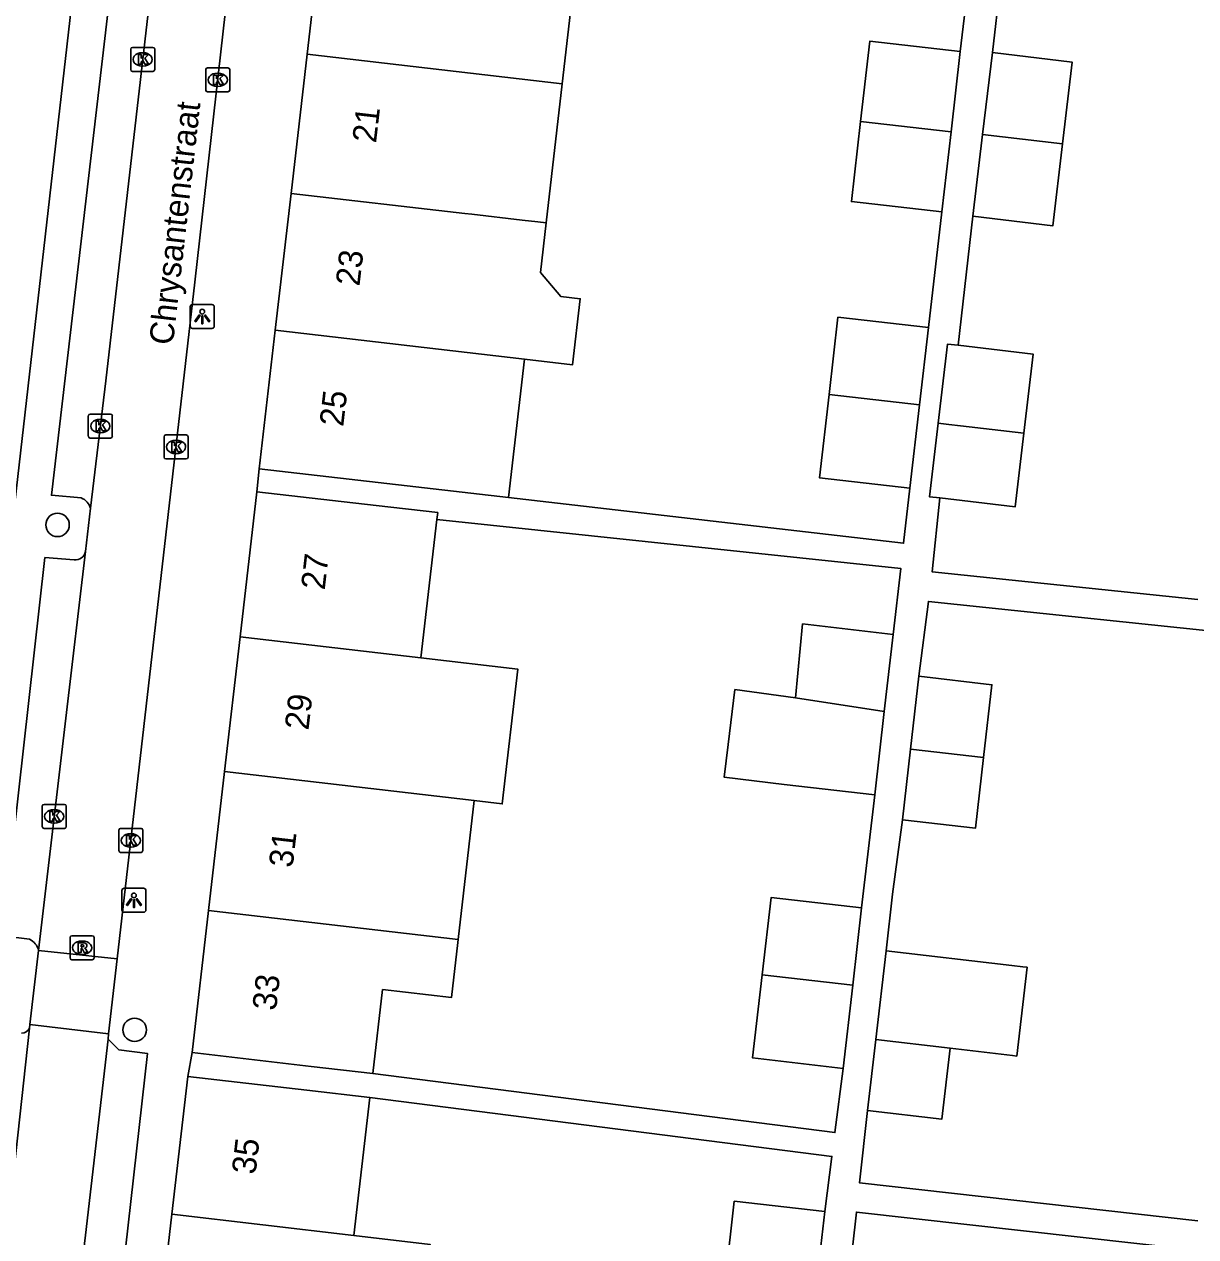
# Model space of a CAD drawing. Extents: x 161696 to 162377, y 380761 to 381673.
# Drawn here: x 162078 to 162126.9, y 381016.9 to 381067.5 of the extents above; entities that cross this region are included whole.
import ezdxf

# ---------------------------------------------------------------- set-up
doc = ezdxf.new("R2010")
doc.units = 0
for name, color, linetype in [('IMGEO_Boom', 7, 'Continuous'), ('IMGEO_Kolk', 7, 'Continuous'), ('IMGEO_Lichtpunt', 7, 'Continuous'), ('IMGEO_Openbare_ruimte_label', 7, 'Continuous'), ('IMGEO_Pand', 7, 'Continuous'), ('IMGEO_Pand_nummerreeks', 7, 'Continuous'), ('IMGEO_Rijbaan_lokaal_open', 7, 'Continuous'), ('IMGEO_Rioolput', 7, 'Continuous'), ('IMGEO_Voetpad_open', 7, 'Continuous')]:
    doc.layers.add(name, color=color, linetype=linetype)

msp = doc.modelspace()

# ---------------------------------------------------------------- linework, layer by layer
at = {"layer": 'IMGEO_Boom'}
for centre in [(162079.43, 381046.631), (162082.645, 381025.565)]:
    msp.add_circle(centre, 0.489, dxfattribs=at)
at = {"layer": 'IMGEO_Kolk'}
for p, q in [((162082.48, 381065.625), (162082.48, 381066.477)), ((162082.555, 381066.551), (162083.407, 381066.551)), ((162082.968, 381066.331), (162082.993, 381066.331)), ((162083.481, 381066.477), (162083.481, 381065.625)), ((162082.991, 381065.771), (162082.966, 381065.771)), ((162083.407, 381065.551), (162082.555, 381065.551)), ((162085.61, 381064.773), (162085.61, 381065.625)), ((162085.685, 381065.699), (162086.537, 381065.699)), ((162086.098, 381065.479), (162086.123, 381065.479)), ((162086.611, 381065.625), (162086.611, 381064.773)), ((162086.121, 381064.919), (162086.096, 381064.919)), ((162086.537, 381064.699), (162085.685, 381064.699)), ((162080.714, 381050.327), (162080.714, 381051.179)), ((162080.789, 381051.253), (162081.641, 381051.253)), ((162081.715, 381051.179), (162081.715, 381050.327)), ((162081.202, 381051.033), (162081.227, 381051.033)), ((162081.641, 381050.253), (162080.789, 381050.253)), ((162081.225, 381050.473), (162081.2, 381050.473)), ((162083.871, 381049.457), (162083.871, 381050.309)), ((162083.946, 381050.383), (162084.798, 381050.383)), ((162084.359, 381050.163), (162084.384, 381050.163)), ((162084.872, 381050.309), (162084.872, 381049.457)), ((162084.382, 381049.603), (162084.357, 381049.603)), ((162084.798, 381049.383), (162083.946, 381049.383)), ((162078.792, 381034.042), (162078.792, 381034.894)), ((162078.867, 381034.968), (162079.719, 381034.968)), ((162079.793, 381034.894), (162079.793, 381034.042)), ((162079.28, 381034.748), (162079.305, 381034.748)), ((162079.719, 381033.968), (162078.867, 381033.968)), ((162079.303, 381034.188), (162079.278, 381034.188)), ((162081.987, 381033.04), (162081.987, 381033.892)), ((162082.062, 381033.966), (162082.914, 381033.966)), ((162082.988, 381033.892), (162082.988, 381033.04)), ((162082.475, 381033.746), (162082.5, 381033.746)), ((162082.914, 381032.966), (162082.062, 381032.966)), ((162082.498, 381033.186), (162082.473, 381033.186))]:
    msp.add_line(p, q, dxfattribs=at)
for points in [[(162082.48, 381065.625), (162082.48, 381066.477)], [(162082.555, 381066.551), (162083.407, 381066.551)], [(162082.801, 381066.251), (162082.924, 381066.251), (162082.924, 381066.1), (162083.054, 381066.251), (162083.218, 381066.251), (162083.072, 381066.1), (162083.225, 381065.851), (162083.073, 381065.851), (162082.988, 381066.015), (162082.924, 381065.948), (162082.924, 381065.851), (162082.801, 381065.851), (162082.801, 381066.251)], [(162083.481, 381066.477), (162083.481, 381065.625)], [(162083.407, 381065.551), (162082.555, 381065.551)], [(162085.61, 381064.773), (162085.61, 381065.625)], [(162085.685, 381065.699), (162086.537, 381065.699)], [(162085.931, 381065.399), (162086.054, 381065.399), (162086.054, 381065.248), (162086.184, 381065.399), (162086.348, 381065.399), (162086.202, 381065.248), (162086.355, 381064.999), (162086.203, 381064.999), (162086.118, 381065.163), (162086.054, 381065.096), (162086.054, 381064.999), (162085.931, 381064.999), (162085.931, 381065.399)], [(162086.611, 381065.625), (162086.611, 381064.773)], [(162086.537, 381064.699), (162085.685, 381064.699)], [(162080.714, 381050.327), (162080.714, 381051.179)], [(162080.789, 381051.253), (162081.641, 381051.253)], [(162081.715, 381051.179), (162081.715, 381050.327)], [(162081.035, 381050.953), (162081.158, 381050.953), (162081.158, 381050.802), (162081.288, 381050.953), (162081.452, 381050.953), (162081.306, 381050.802), (162081.459, 381050.553), (162081.307, 381050.553), (162081.222, 381050.717), (162081.158, 381050.65), (162081.158, 381050.553), (162081.035, 381050.553), (162081.035, 381050.953)], [(162081.641, 381050.253), (162080.789, 381050.253)], [(162083.871, 381049.457), (162083.871, 381050.309)], [(162083.946, 381050.383), (162084.798, 381050.383)], [(162084.192, 381050.083), (162084.315, 381050.083), (162084.315, 381049.932), (162084.445, 381050.083), (162084.609, 381050.083), (162084.463, 381049.932), (162084.616, 381049.683), (162084.464, 381049.683), (162084.379, 381049.847), (162084.315, 381049.78), (162084.315, 381049.683), (162084.192, 381049.683), (162084.192, 381050.083)], [(162084.872, 381050.309), (162084.872, 381049.457)], [(162084.798, 381049.383), (162083.946, 381049.383)], [(162078.792, 381034.042), (162078.792, 381034.894)], [(162078.867, 381034.968), (162079.719, 381034.968)], [(162079.793, 381034.894), (162079.793, 381034.042)], [(162079.113, 381034.668), (162079.236, 381034.668), (162079.236, 381034.517), (162079.366, 381034.668), (162079.53, 381034.668), (162079.384, 381034.517), (162079.537, 381034.268), (162079.385, 381034.268), (162079.3, 381034.432), (162079.236, 381034.365), (162079.236, 381034.268), (162079.113, 381034.268), (162079.113, 381034.668)], [(162079.719, 381033.968), (162078.867, 381033.968)], [(162081.987, 381033.04), (162081.987, 381033.892)], [(162082.062, 381033.966), (162082.914, 381033.966)], [(162082.988, 381033.892), (162082.988, 381033.04)], [(162082.308, 381033.666), (162082.431, 381033.666), (162082.431, 381033.515), (162082.561, 381033.666), (162082.725, 381033.666), (162082.579, 381033.515), (162082.732, 381033.266), (162082.58, 381033.266), (162082.495, 381033.43), (162082.431, 381033.363), (162082.431, 381033.266), (162082.308, 381033.266), (162082.308, 381033.666)], [(162082.914, 381032.966), (162082.062, 381032.966)]]:
    msp.add_lwpolyline(points, dxfattribs=at)
for centre, start, end in [((162082.557, 381066.475), 91.552, 178.448), ((162082.557, 381066.475), 91.552, 178.448), ((162083.405, 381066.475), 1.552, 88.448), ((162083.405, 381066.475), 1.552, 88.448), ((162082.557, 381065.627), 181.552, 268.448), ((162082.557, 381065.627), 181.552, 268.448), ((162083.405, 381065.627), 271.552, 358.448), ((162083.405, 381065.627), 271.552, 358.448), ((162085.687, 381065.623), 91.552, 178.448), ((162085.687, 381065.623), 91.552, 178.448), ((162086.535, 381065.623), 1.552, 88.448), ((162086.535, 381065.623), 1.552, 88.448), ((162085.687, 381064.775), 181.552, 268.448), ((162085.687, 381064.775), 181.552, 268.448), ((162086.535, 381064.775), 271.552, 358.448), ((162086.535, 381064.775), 271.552, 358.448), ((162080.791, 381051.177), 91.552, 178.448), ((162080.791, 381051.177), 91.552, 178.448), ((162081.639, 381051.177), 1.552, 88.448), ((162081.639, 381051.177), 1.552, 88.448), ((162080.791, 381050.329), 181.552, 268.448), ((162080.791, 381050.329), 181.552, 268.448), ((162081.639, 381050.329), 271.552, 358.448), ((162081.639, 381050.329), 271.552, 358.448), ((162083.948, 381050.307), 91.552, 178.448), ((162083.948, 381050.307), 91.552, 178.448), ((162084.796, 381050.307), 1.552, 88.448), ((162084.796, 381050.307), 1.552, 88.448), ((162083.948, 381049.459), 181.552, 268.448), ((162083.948, 381049.459), 181.552, 268.448), ((162084.796, 381049.459), 271.552, 358.448), ((162084.796, 381049.459), 271.552, 358.448), ((162078.869, 381034.892), 91.552, 178.448), ((162078.869, 381034.892), 91.552, 178.448), ((162079.717, 381034.892), 1.552, 88.448), ((162079.717, 381034.892), 1.552, 88.448), ((162078.869, 381034.044), 181.552, 268.448), ((162078.869, 381034.044), 181.552, 268.448), ((162079.717, 381034.044), 271.552, 358.448), ((162079.717, 381034.044), 271.552, 358.448), ((162082.064, 381033.89), 91.552, 178.448), ((162082.064, 381033.89), 91.552, 178.448), ((162082.912, 381033.89), 1.552, 88.448), ((162082.912, 381033.89), 1.552, 88.448), ((162082.064, 381033.042), 181.552, 268.448), ((162082.064, 381033.042), 181.552, 268.448), ((162082.912, 381033.042), 271.552, 358.448), ((162082.912, 381033.042), 271.552, 358.448)]:
    msp.add_arc(centre, 0.0765, start, end, dxfattribs=at)
for centre, major_axis, ratio, start_param, end_param in [((162082.967, 381066.051), (-0.387, 0.002), 0.722429, 4.712389, 7.853982), ((162082.992, 381066.051), (-0.39, 0.002), 0.717154, 1.570796, 4.712389), ((162086.097, 381065.199), (-0.387, 0.002), 0.722429, 4.712389, 7.853982), ((162086.122, 381065.199), (-0.39, 0.002), 0.717154, 1.570796, 4.712389), ((162081.201, 381050.753), (-0.387, 0.002), 0.722429, 4.712389, 7.853982), ((162081.226, 381050.753), (-0.39, 0.002), 0.717154, 1.570796, 4.712389), ((162084.358, 381049.883), (-0.387, 0.002), 0.722429, 4.712389, 7.853982), ((162084.383, 381049.883), (-0.39, 0.002), 0.717154, 1.570796, 4.712389), ((162079.279, 381034.468), (-0.387, 0.002), 0.722429, 4.712389, 7.853982), ((162079.304, 381034.468), (-0.39, 0.002), 0.717154, 1.570796, 4.712389), ((162082.474, 381033.466), (-0.387, 0.002), 0.722429, 4.712389, 7.853982), ((162082.499, 381033.466), (-0.39, 0.002), 0.717154, 1.570796, 4.712389)]:
    msp.add_ellipse(centre, major_axis=major_axis, ratio=ratio, start_param=start_param, end_param=end_param, dxfattribs=at)
at = {"layer": 'IMGEO_Lichtpunt'}
for p, q in [((162084.967, 381055.73), (162084.967, 381054.923)), ((162084.967, 381055.73), (162084.967, 381054.923)), ((162085.869, 381055.825), (162085.061, 381055.825)), ((162085.869, 381055.825), (162085.061, 381055.825)), ((162085.963, 381054.923), (162085.963, 381055.73)), ((162085.963, 381054.923), (162085.963, 381055.73)), ((162085.061, 381054.829), (162085.869, 381054.829)), ((162085.061, 381054.829), (162085.869, 381054.829)), ((162082.117, 381031.375), (162082.117, 381030.568)), ((162082.117, 381031.375), (162082.117, 381030.568)), ((162083.019, 381031.47), (162082.211, 381031.47)), ((162083.019, 381031.47), (162082.211, 381031.47)), ((162083.113, 381030.568), (162083.113, 381031.375)), ((162083.113, 381030.568), (162083.113, 381031.375)), ((162082.211, 381030.474), (162083.019, 381030.474)), ((162082.211, 381030.474), (162083.019, 381030.474))]:
    msp.add_line(p, q, dxfattribs=at)
for points in [[(162085.341, 381055.394), (162085.38, 381055.366), (162085.192, 381055.104), (162085.154, 381055.131), (162085.341, 381055.394)], [(162085.443, 381055.346), (162085.49, 381055.346), (162085.49, 381055.024), (162085.443, 381055.024), (162085.443, 381055.346)], [(162085.553, 381055.366), (162085.591, 381055.393), (162085.778, 381055.131), (162085.739, 381055.103), (162085.553, 381055.366)], [(162082.491, 381031.039), (162082.53, 381031.011), (162082.342, 381030.749), (162082.304, 381030.776), (162082.491, 381031.039)], [(162082.593, 381030.991), (162082.64, 381030.991), (162082.64, 381030.669), (162082.593, 381030.669), (162082.593, 381030.991)], [(162082.703, 381031.011), (162082.741, 381031.038), (162082.928, 381030.776), (162082.889, 381030.748), (162082.703, 381031.011)]]:
    msp.add_lwpolyline(points, dxfattribs=at)
for centre in [(162085.466, 381055.528), (162082.616, 381031.173)]:
    msp.add_circle(centre, 0.0994, dxfattribs=at)
for centre, start, end in [((162085.061, 381055.73), 90, 180), ((162085.061, 381055.73), 90, 180), ((162085.869, 381055.73), 0, 90), ((162085.869, 381055.73), 0, 90), ((162085.061, 381054.923), 180, 270), ((162085.061, 381054.923), 180, 270), ((162085.869, 381054.923), 270, 0), ((162085.869, 381054.923), 270, 360), ((162082.211, 381031.375), 90, 180), ((162082.211, 381031.375), 90, 180), ((162083.019, 381031.375), 0, 90), ((162083.019, 381031.375), 0, 90), ((162082.211, 381030.568), 180, 270), ((162082.211, 381030.568), 180, 270), ((162083.019, 381030.568), 270, 0), ((162083.019, 381030.568), 270, 360)]:
    msp.add_arc(centre, 0.0946, start, end, dxfattribs=at)
at = {"layer": 'IMGEO_Pand'}
for points in [[(162089.842, 381066.266), (162090.553, 381072.412)], [(162101.193, 381071.182), (162100.482, 381065.034)], [(162112.924, 381063.463), (162113.308, 381066.809), (162117.083, 381066.376)], [(162089.171, 381060.461), (162089.842, 381066.266)], [(162100.482, 381065.034), (162089.842, 381066.266)], [(162117.083, 381066.376), (162116.7, 381063.031)], [(162118.015, 381062.918), (162118.421, 381066.332)], [(162118.421, 381066.332), (162121.756, 381065.935), (162121.35, 381062.522)], [(162099.811, 381059.23), (162100.482, 381065.034)], [(162116.316, 381059.685), (162112.541, 381060.118), (162112.924, 381063.463)], [(162116.7, 381063.031), (162112.924, 381063.463)], [(162116.7, 381063.031), (162116.316, 381059.685)], [(162117.609, 381059.505), (162118.015, 381062.918)], [(162121.35, 381062.522), (162118.015, 381062.918)], [(162121.35, 381062.522), (162120.944, 381059.108), (162117.609, 381059.505)], [(162088.511, 381054.749), (162089.171, 381060.461)], [(162099.811, 381059.23), (162099.462, 381059.27), (162098.804, 381059.347), (162096.715, 381059.588), (162096.412, 381059.623), (162089.171, 381060.461)], [(162098.907, 381053.545), (162100.912, 381053.313), (162101.231, 381056.068), (162100.42, 381056.162), (162099.883, 381056.792), (162099.571, 381057.157), (162099.811, 381059.23)], [(162111.608, 381052.074), (162111.977, 381055.292), (162115.752, 381054.859)], [(162087.843, 381048.974), (162088.511, 381054.749)], [(162088.511, 381054.749), (162098.907, 381053.545)], [(162115.752, 381054.859), (162115.383, 381051.637)], [(162116.993, 381054.124), (162116.551, 381054.177), (162116.158, 381050.877)], [(162119.732, 381050.461), (162120.124, 381053.751), (162116.993, 381054.124)], [(162098.244, 381047.771), (162098.907, 381053.545)], [(162114.985, 381048.168), (162111.21, 381048.601), (162111.608, 381052.074)], [(162115.383, 381051.637), (162111.608, 381052.074)], [(162115.383, 381051.637), (162114.985, 381048.168)], [(162116.231, 381047.756), (162115.793, 381047.808), (162116.158, 381050.877)], [(162116.158, 381050.877), (162116.599, 381050.826), (162117.09, 381050.769), (162119.732, 381050.461)], [(162116.231, 381047.756), (162119.366, 381047.382), (162119.732, 381050.461)], [(162098.244, 381047.771), (162092.81, 381048.4), (162087.843, 381048.974)], [(162087.046, 381041.954), (162087.747, 381048.013)], [(162087.747, 381048.013), (162092.714, 381047.439), (162095.285, 381047.142), (162095.251, 381046.849)], [(162095.251, 381046.849), (162094.585, 381041.081)], [(162110.205, 381039.42), (162110.508, 381042.498), (162114.283, 381042.065)], [(162086.398, 381036.348), (162087.046, 381041.954)], [(162087.046, 381041.954), (162094.585, 381041.081)], [(162114.283, 381042.065), (162113.914, 381038.844)], [(162094.585, 381041.081), (162098.627, 381040.613), (162097.976, 381034.991), (162096.808, 381035.126)], [(162115.006, 381037.278), (162115.354, 381040.313)], [(162118.052, 381036.923), (162118.401, 381039.963), (162115.354, 381040.313)], [(162113.516, 381035.374), (162109.741, 381035.807), (162107.232, 381036.108), (162107.401, 381037.466), (162107.686, 381039.759), (162110.205, 381039.42)], [(162113.914, 381038.844), (162110.205, 381039.42)], [(162113.914, 381038.844), (162113.516, 381035.374)], [(162114.668, 381034.328), (162115.006, 381037.278)], [(162114.668, 381034.328), (162117.714, 381033.978), (162118.052, 381036.923)], [(162118.052, 381036.923), (162115.006, 381037.278)], [(162085.727, 381030.539), (162086.398, 381036.348)], [(162096.808, 381035.126), (162086.398, 381036.348)], [(162096.139, 381029.333), (162096.808, 381035.126)], [(162108.82, 381027.865), (162109.189, 381031.082), (162112.964, 381030.649)], [(162085.042, 381024.616), (162085.727, 381030.539)], [(162096.139, 381029.333), (162085.727, 381030.539)], [(162112.964, 381030.649), (162112.595, 381027.428)], [(162092.583, 381023.744), (162092.988, 381027.242), (162095.859, 381026.91), (162096.125, 381029.213), (162096.139, 381029.333)], [(162113.555, 381025.158), (162113.987, 381028.861)], [(162116.655, 381024.796), (162119.264, 381024.491), (162119.44, 381024.47), (162119.873, 381028.174), (162119.697, 381028.194), (162119.233, 381028.249), (162113.987, 381028.861)], [(162112.197, 381023.958), (162108.422, 381024.391), (162108.82, 381027.865)], [(162112.595, 381027.428), (162108.82, 381027.865)], [(162112.595, 381027.428), (162112.197, 381023.958)], [(162113.21, 381022.199), (162113.555, 381025.158)], [(162113.21, 381022.199), (162116.31, 381021.837), (162116.655, 381024.796)], [(162116.655, 381024.796), (162113.555, 381025.158)], [(162092.583, 381023.744), (162090.009, 381024.042), (162085.042, 381024.616)], [(162084.196, 381017.874), (162084.861, 381023.624)], [(162084.861, 381023.624), (162089.828, 381023.05), (162092.453, 381022.746)], [(162091.782, 381016.988), (162092.453, 381022.746)], [(162107.286, 381015.177), (162107.658, 381018.417), (162111.433, 381017.984)], [(162083.524, 381012.063), (162084.196, 381017.874)], [(162084.196, 381017.874), (162091.782, 381016.988)], [(162111.433, 381017.984), (162111.061, 381014.736)], [(162094.295, 381010.804), (162094.971, 381016.616), (162091.782, 381016.988)]]:
    msp.add_lwpolyline(points, dxfattribs=at)
at = {"layer": 'IMGEO_Rijbaan_lokaal_open'}
for points in [[(162086.824, 381071.549), (162085.16, 381056.755), (162081.92, 381028.524)], [(162080.81, 381047.325), (162081.438, 381052.634), (162083.429, 381069.944)], [(162080.597, 381045.518), (162080.81, 381047.325)], [(162078.639, 381028.879), (162079.774, 381038.563), (162080.597, 381045.518)], [(162078.276, 381025.782), (162078.639, 381028.879)], [(162081.92, 381028.524), (162078.639, 381028.879)], [(162081.92, 381028.524), (162081.562, 381025.405)], [(162078.26, 381025.633), (162078.276, 381025.782)], [(162081.562, 381025.405), (162078.276, 381025.782)], [(162076.389, 381008.55), (162078.26, 381025.633)], [(162081.562, 381025.405), (162081.535, 381025.173)], [(162081.535, 381025.173), (162080.596, 381016.993), (162078.552, 381000), (162078.155, 380996.635)]]:
    msp.add_lwpolyline(points, dxfattribs=at)
at = {"layer": 'IMGEO_Rioolput'}
for p, q in [((162079.953, 381028.565), (162079.953, 381029.417)), ((162080.028, 381029.491), (162080.88, 381029.491)), ((162080.954, 381029.417), (162080.954, 381028.565)), ((162080.441, 381029.271), (162080.466, 381029.271)), ((162080.88, 381028.491), (162080.028, 381028.491)), ((162080.464, 381028.711), (162080.439, 381028.711))]:
    msp.add_line(p, q, dxfattribs=at)
for points in [[(162079.953, 381028.565), (162079.953, 381029.417)], [(162080.028, 381029.491), (162080.88, 381029.491)], [(162080.954, 381029.417), (162080.954, 381028.565)], [(162080.542, 381029.189), (162080.29, 381029.191), (162080.29, 381028.791)], [(162080.29, 381028.791), (162080.414, 381028.791), (162080.414, 381028.953), (162080.425, 381028.953)], [(162080.468, 381029.11), (162080.414, 381029.11), (162080.414, 381029.029)], [(162080.414, 381029.029), (162080.466, 381029.029)], [(162080.472, 381028.924), (162080.543, 381028.791), (162080.683, 381028.791), (162080.618, 381028.917)], [(162080.88, 381028.491), (162080.028, 381028.491)]]:
    msp.add_lwpolyline(points, dxfattribs=at)
for centre, radius, start, end in [((162080.03, 381029.415), 0.0765, 91.552, 178.448), ((162080.03, 381029.415), 0.0765, 91.552, 178.448), ((162080.878, 381029.415), 0.0765, 1.552, 88.448), ((162080.878, 381029.415), 0.0765, 1.552, 88.448), ((162080.424, 381028.9), 0.0533, 26.0293, 88.6989), ((162080.45, 381029.218), 0.19, 274.7715, 282.9687), ((162080.474, 381029.014), 0.0964, 77.0061, 93.1865), ((162080.488, 381029.071), 0.0378, 276.6634, 79.6772), ((162080.541, 381029.079), 0.109, 350.3612, 89.416), ((162080.539, 381029.079), 0.112, 277.5842, 350.9817), ((162080.523, 381028.864), 0.108, 29.5134, 73.7905), ((162080.03, 381028.567), 0.0765, 181.552, 268.448), ((162080.03, 381028.567), 0.0765, 181.552, 268.448), ((162080.878, 381028.567), 0.0765, 271.552, 358.448), ((162080.878, 381028.567), 0.0765, 271.552, 358.448)]:
    msp.add_arc(centre, radius, start, end, dxfattribs=at)
for centre, major_axis, ratio, start_param, end_param in [((162080.44, 381028.991), (-0.387, 0.002), 0.722429, 4.712389, 7.853982), ((162080.465, 381028.991), (-0.39, 0.002), 0.717154, 1.570796, 4.712389)]:
    msp.add_ellipse(centre, major_axis=major_axis, ratio=ratio, start_param=start_param, end_param=end_param, dxfattribs=at)
at = {"layer": 'IMGEO_Voetpad_open'}
for points in [[(162069.905, 380982.626), (162072.098, 381000), (162073.358, 381009.985), (162080.609, 381073.546)], [(162101.193, 381071.182), (162117.423, 381069.291), (162117.083, 381066.376)], [(162080.417, 381047.758), (162079.172, 381047.869), (162081.727, 381069.672), (162082.78, 381069.599)], [(162118.421, 381066.332), (162118.748, 381069.136), (162132.798, 381067.511)], [(162116.316, 381059.685), (162115.752, 381054.859)], [(162116.993, 381054.124), (162117.609, 381059.505)], [(162087.843, 381048.974), (162087.747, 381048.013)], [(162114.985, 381048.168), (162114.721, 381045.864), (162098.244, 381047.771)], [(162126.992, 381043.513), (162115.908, 381044.678), (162116.231, 381047.756)], [(162095.251, 381046.849), (162114.6, 381044.815), (162114.283, 381042.065)], [(162078.257, 381029.346), (162077.14, 381029.482), (162078.902, 381045.265), (162080.121, 381045.168)], [(162115.354, 381040.313), (162115.757, 381043.44), (162129.836, 381041.96)], [(162113.516, 381035.374), (162112.964, 381030.649)], [(162113.987, 381028.861), (162114.262, 381031.218), (162114.668, 381034.328)], [(162081.535, 381025.173), (162081.992, 381024.724), (162083.186, 381024.576), (162080.413, 381000), (162080.067, 380997.004), (162078.879, 380997.149)], [(162085.042, 381024.616), (162084.861, 381023.624)], [(162112.197, 381023.958), (162111.854, 381021.281), (162092.583, 381023.744)], [(162092.453, 381022.746), (162111.727, 381020.283), (162111.433, 381017.984)], [(162126.995, 381017.6), (162112.885, 381019.181), (162113.21, 381022.199)], [(162112.415, 381014.985), (162112.748, 381017.959), (162126.817, 381016.382)]]:
    msp.add_lwpolyline(points, dxfattribs=at)
for centre, radius, start, end in [((162080.134, 381047.107), 0.71, 17.9094, 66.5457), ((162080.167, 381045.604), 0.439, 263.9878, 348.6659), ((162077.961, 381028.714), 0.698, 13.6725, 64.893), ((162077.929, 381025.787), 0.365, 269.8135, 335.0618)]:
    msp.add_arc(centre, radius, start, end, dxfattribs=at)

# ---------------------------------------------------------------- texts
at = {"layer": 'IMGEO_Openbare_ruimte_label'}
msp.add_text('Chrysantenstraat', height=1, rotation=83.5143, dxfattribs=at).set_placement((162084.24, 381054.104))
at = {"layer": 'IMGEO_Pand_nummerreeks'}
for s, rotation, p in [('21', 83.4055, (162092.713, 381062.538)), ('23', 83.4055, (162092.022, 381056.565)), ('25', 83.4045, (162091.345, 381050.706)), ('27', 83.4055, (162090.572, 381043.89)), ('29', 83.4051, (162089.895, 381038.041)), ('31', 83.4051, (162089.232, 381032.305)), ('33', 83.4051, (162088.543, 381026.343)), ('35', 83.4049, (162087.686, 381019.504))]:
    msp.add_text(s, height=1, rotation=rotation, dxfattribs=at).set_placement(p)

doc.saveas('drawing.dxf')
